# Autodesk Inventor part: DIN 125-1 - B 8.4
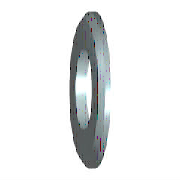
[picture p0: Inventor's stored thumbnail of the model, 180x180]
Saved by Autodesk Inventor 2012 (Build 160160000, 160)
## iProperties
Company: CAD-Verlag
Comments: To add or edit properties for Autodesk Inventor files, use iProperties.
Shininess: 64.0
Length Units: 11269
Angle Units: 11279
Time Units: 11290
Mass Units: 11283
Length Display Precision: 3
Angle Display Precision: 2
Compacted: True
Alert: To add or edit properties for Autodesk Inventor files, use iProperties.
Created: 2004-09
Part Number: DIN 125-1 - B 8.4
Vendor: Autodesk Inc.
Document SubType Name: Modeling
Designer: Greiling
Material: Standard
Description: Scheibe
Standard: DIN 125-1
Size Designation: B 8.4
Density: 1 g/cm^3
Density: 0.0
Volumn: 0.0
Area: 0.0
PropertySet Name: Model Information
Control State: 0
Master: False
Checked Out: False
Classification: un/spsc 31161807
Author: Jürgen Kronas
Revision Number: 8
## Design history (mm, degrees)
sketch "Skizze"
  geometry: C1 r 8 at (0, 0); C2 r 4.2 at (0, 0); 1 further point
  constraints: 2 centre point, 2 coincident
  dimensions: "d0" = 8.4 diameter of C2 (= SD1); "d1" = 16 diameter of C1 (= SD2)
extrude "Körper" new body sketch "Skizze" distance "d2" = 1.6 (= SD); taper "d3" = 0 deg
node "Volumenkörper1"
node "Volumenkörpern"
node "Oberflächenkörpern"
chamfer "Fase" distance "d4" = 0.4 (= PHH); stored, may be unused: angle "d5" = 45 deg, second distance "d8" = 0.4 (= PHH)
other parameters: "SD1" = 8.4 [user parameter; used in 1 equation term], "SD2" = 16 [user parameter; used in 1 equation term], "SD" = 1.6 [user parameter; used in 1 equation term], "PHH" = 0.4 [user parameter; used in 2 equation terms], "FAWI" = 45 deg [user parameter], "d6" = 0, "d7" = 0, "NND" = 8 [user parameter]
